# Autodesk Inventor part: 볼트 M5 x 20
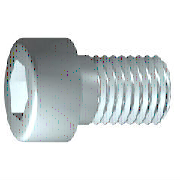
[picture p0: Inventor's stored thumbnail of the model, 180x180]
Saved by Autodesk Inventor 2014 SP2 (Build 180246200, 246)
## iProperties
Created: 2012-02
Part Number: 볼트 M5 x 20
Material: 스테인리스강
Description: 6각 소켓 머리 캡 나사
Document SubType Name: Modeling
Standard: ISO 4762
Designer: mduedu
Standard Revision: Fourth edition 2004-03-01
Standards Organization: ISO
Language: ko-KR
Size Designation: M5 x 20
Categories: <MemberInstance><Categories><Category DisplayName="조임쇠" InternalName="e4da775c-781d-43d5-af7c-5136215cf5a6" Mnemonic="FSTN"><Category DisplayName="볼트" InternalN
Density: 8.08 g/cm^3
Mass: 5.10181 g
Surface Area: 5.88237 cm^2
Volume: 0.631412 cm^3
Appearance: 반광택
IsCustomPart: 0
Author: mduedu
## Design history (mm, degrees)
sketch "스케치1"
  geometry: L1 (-1.167, 0)-(20, 0); L2 (20, 0)-(20, 2.5); L3 (20, 2.5)-(2, 2.5); L4 (2, 2.5)-(1.509, 2.5); L5 (1.509, 2.5)-(0, 2.5); L6 (0, 2.5)-(0, 4.25); L7 (0, 4.25)-(-5, 4.25); L8 (-5, 4.25)-(-5, 2.309); L9 (-5, 2.309)-(-2.5, 2.309); L10 (-2.5, 2.309)-(-1.167, 0); L11 (-10, 0)-(25, 0) reference; L12 (0, -0.85)-(0, 5.1) reference; L13 (2, 2.5)-(0, 2.5)
  constraints: 22 end point, 6 parallel, 2 collinear, 2 perpendicular, 1 horizontal, 1 point on line
  dimensions: "d1" = 18 distance from line of L3.end L2 (= GEL); "d2" = 0.49086 distance of L4.end L3.end (computed from GAL); "d3" = 5 distance between parallel lines of L8 L6 (= KOH); "d4" = 2.5 distance of L8.end L9.end (= INTI); "d5" = 60 deg angle of L10 L1; "d6" = 5 diameter of L3 L1 (= GD); "d7" = 5 diameter of L5 L1 (= BDM); "d8" = 4.6188 diameter of L9 L1 (= 1.1547 x SW); "d9" = 8.5 diameter of L7 L1 (= KOD); "d26" = 20 distance between parallel lines of L12 L2 (= NLG)
revolve "본체" sketch "스케치1" stored, may be unused: angle "d10" = 90 deg
sketch "스케치2"
  geometry: L1 (0, -5.95)-(0, 5.95) reference; L2 (-5.95, 0)-(5.95, 0) reference; L3 (2.309, 0)-(1.155, -2); L4 (1.155, -2)-(-1.155, -2); L5 (-1.155, -2)-(-2.309, 0); L6 (-2.309, 0)-(-1.155, 2); L7 (-1.155, 2)-(1.155, 2); L8 (1.155, 2)-(2.309, 0); 2 further points
  constraints: 12 end point, 1 coincident, 1 horizontal alignment, 1 point on line, 12 other
extrude "슬롯" join sketch "스케치2" stored distance "d11" = 10; taper "d12" = 0 deg
workplane "Work Plane1"
fillet "Fillet2" dims "d30" = 0.1 (= R)
body "Solid1"
fillet "모깎기1" dims "d17" = 0.5 (= RR)
feature "스레드" dims "d13" = 18 (= GEL), "d14" = 0
chamfer "모따기1" distance "d15" = 0.49076 (= -0.5 x SPD + 0.5 x GD); stored, may be unused: second distance "d16" = 0.49076 (= GUL), angle "d27" = 45 deg
other parameters: "GD" = 5 [user parameter; used in 2 equation terms], "NLG" = 20 [user parameter; used in 1 equation term], "GEL" = 18 [user parameter; used in 2 equation terms], "KOD" = 8.5 [user parameter; used in 1 equation term], "KOH" = 5 [user parameter; used in 1 equation term], "INTI" = 2.5 [user parameter; used in 1 equation term], "GAL" = 0.49076 (= 0.61345 x PTC) [user parameter; used in 1 equation term], "GUL" = 0.49076 (= 0.61345 x PTC) [user parameter; used in 1 equation term], "BDM" = 5 (= NND) [user parameter; used in 1 equation term], "SW" = 4 [user parameter; used in 2 equation terms], "RR" = 0.5 [user parameter; used in 1 equation term], "SPD" = 4.01848 (= NND - 1.2269 x PTC) [user parameter; used in 1 equation term], "d19" = 0, "d28" = 0, "d29" = 0, "R" = 0.1 [user parameter; used in 1 equation term], "TOA" = 30 deg [user parameter], "GD1" = 4.01848 (= THREADDIA - 1.2269 x PTC) [user parameter], "THREADDIA" = 5 [user parameter; used in 1 equation term], "FAWI" = 45 deg [user parameter], "TPU" = 12.5 (computed from PTC) [user parameter], "PTC" = 0.8 [user parameter; used in 5 equation terms], "NND" = 5 [user parameter; used in 2 equation terms], "E0" = 4.62 (= 1.155 x SW) [user parameter]
